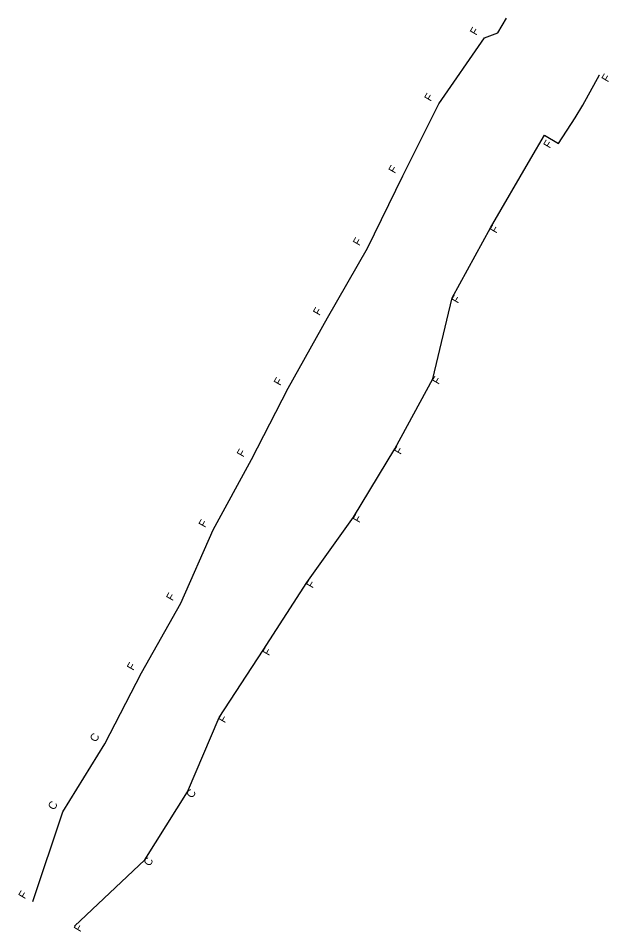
# Model space of a CAD drawing. Extents: x 2138032 to 2141442, y 405316 to 410985.
# Drawn here: x 2140665 to 2141034, y 409721 to 410291 of the extents above; entities that cross this region are included whole.
import ezdxf

# ---------------------------------------------------------------- set-up
doc = ezdxf.new("R2010")
doc.units = 0
for name, color, linetype in [('Prop Retaining Wall', 7, 'Continuous'), ('Prop SBG', 7, 'Continuous'), ('Scratch_Level_6', 7, 'Continuous'), ('Scratch_Level_7', 7, 'Continuous')]:
    doc.layers.add(name, color=color, linetype=linetype)

msp = doc.modelspace()

# ---------------------------------------------------------------- linework, layer by layer
at = {"layer": 'Prop Retaining Wall'}
for p, q in [((2140692.74, 409795.63), (2140718.91, 409838.11)), ((2140743.92, 409765.62), (2140770.6, 409808.1))]:
    msp.add_line(p, q, dxfattribs=at)
at = {"layer": 'Prop SBG'}
for p, q in [((2140718.91, 409838.11), (2140741.91, 409882.43)), ((2140770.6, 409808.1), (2140790.41, 409854.56)), ((2140673.98, 409739.63), (2140692.74, 409795.63)), ((2140700.02, 409724.17), (2140743.92, 409765.62))]:
    msp.add_line(p, q, dxfattribs=at)
at = {"layer": 'Scratch_Level_6'}
for p, q in [((2140927.72, 410237.7), (2140956.23, 410278.93)), ((2141017.81, 410236.99), (2141028.27, 410255.94)), ((2141028.27, 410255.94), (2141028.27, 410255.94)), ((2140905.32, 410192.72), (2140927.72, 410237.7)), ((2141013.01, 410228.98), (2141017.81, 410236.99)), ((2141002.64, 410213.01), (2141013.01, 410228.98)), ((2140985.25, 410203.56), (2140993.83, 410218.23)), ((2140993.83, 410218.23), (2141002.64, 410213.01)), ((2140960.12, 410160.41), (2140985.25, 410203.56)), ((2140883.13, 410147.57), (2140905.32, 410192.72)), ((2140936.16, 410116.62), (2140960.12, 410160.41)), ((2140858.2, 410104.03), (2140883.13, 410147.57)), ((2140924.04, 410066), (2140936.16, 410116.62)), ((2140833.68, 410060.26), (2140858.2, 410104.03)), ((2140900.28, 410022.2), (2140924.04, 410066)), ((2140810.6, 410015.69), (2140833.68, 410060.26)), ((2140874.45, 409979.57), (2140900.28, 410022.2)), ((2140786.72, 409971.66), (2140810.6, 410015.69)), ((2140845.27, 409938.73), (2140874.45, 409979.57)), ((2140766.43, 409925.85), (2140786.72, 409971.66)), ((2140817.98, 409896.55), (2140845.27, 409938.73)), ((2140741.91, 409882.43), (2140766.43, 409925.85)), ((2140790.41, 409854.56), (2140817.98, 409896.55))]:
    msp.add_line(p, q, dxfattribs=at)
msp.add_lwpolyline([(2140956.23, 410278.93), (2140964.71, 410282.04), (2140970.02, 410291.18)], dxfattribs=at)

# ---------------------------------------------------------------- texts
at = {"layer": 'Scratch_Level_7'}
for s, rotation, p in [('F', 59.3093, (2140951.13, 410280.12)), ('F', 59.3093, (2141033.4, 410250.91)), ('F', 59.3093, (2140922.62, 410238.9)), ('F', 59.3093, (2140997.06, 410209.58)), ('F', 59.476, (2140900.21, 410193.9)), ('F', 59.476, (2140963.63, 410156.51)), ('F', 59.734, (2140878.02, 410148.72)), ('F', 59.734, (2140939.68, 410112.74)), ('F', 59.9921, (2140853.08, 410105.17)), ('F', 59.9921, (2140927.58, 410062.14)), ('F', 60.2502, (2140828.56, 410061.38)), ('F', 60.5083, (2140805.47, 410016.78)), ('F', 60.2502, (2140903.84, 410018.35)), ('F', 60.6404, (2140781.59, 409972.74)), ('F', 60.5083, (2140878.03, 409975.74)), ('F', 60.6404, (2140848.85, 409934.9)), ('F', 60.3823, (2140761.3, 409926.96)), ('F', 60.3823, (2140821.55, 409892.71)), ('F', 60.1242, (2140736.73, 409883.46)), ('F', 60.1242, (2140793.96, 409850.71)), ('C', 59.8661, (2140713.5, 409838.75)), ('C', 59.8661, (2140773.84, 409803.72)), ('C', 59.608, (2140687.33, 409796.29)), ('C', 59.608, (2140747.13, 409761.22)), ('F', 59.3093, (2140668.87, 409740.82)), ('F', 59.3093, (2140703.52, 409720.26))]:
    msp.add_text(s, height=5, rotation=rotation, dxfattribs=at).set_placement(p)

doc.saveas('drawing.dxf')
